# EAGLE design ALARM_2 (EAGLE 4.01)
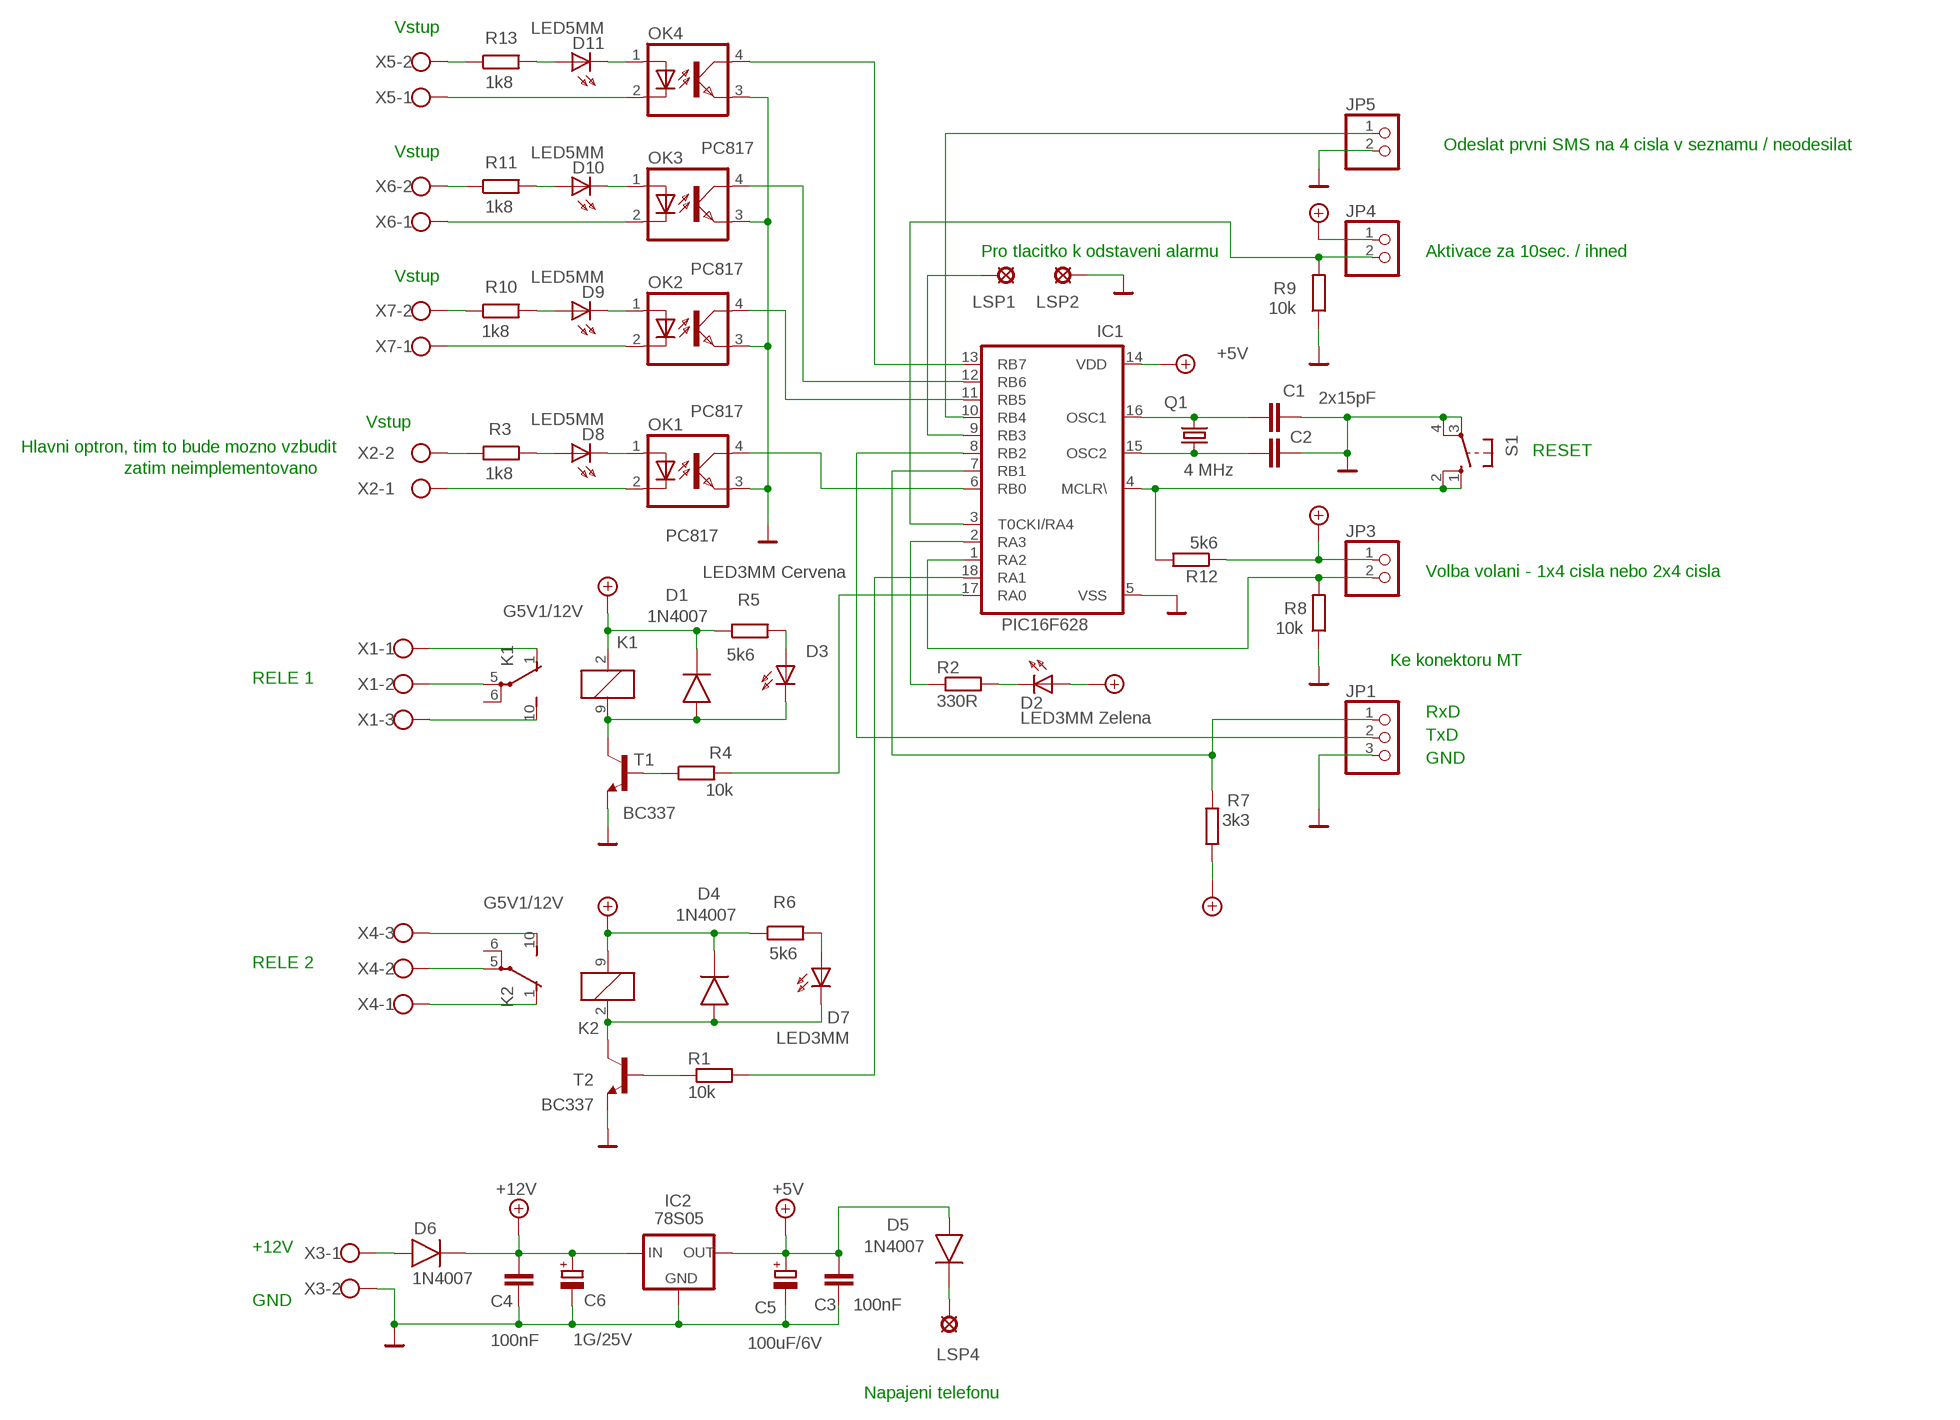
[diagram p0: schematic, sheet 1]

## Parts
C1  2x15pF  C-EU025-025X050  [C025-025X050]
C2  C-EU025-025X050  [C025-025X050]
C3  100nF  C-EU025-025X050  [C025-025X050]
C4  100nF  C-EU025-025X050  [C025-025X050]
C5  100uF/6V  CPOL-EUE2.5-7  [E2,5-7]
C6  1G/25V  CPOL-EUE5-13  [E5-13]
D1  1N4007  [DO41]
D2  LED3MM Zelena  LED3MM  [LED3MM]
D3  LED3MM Cervena  LED3MM  [LED3MM]
D4  1N4007  [DO41]
D5  1N4007  [DO41]
D6  1N4007  [DO41]
D7  LED3MM  [LED3MM]
D8  LED5MM  [LED5MM]
D9  LED5MM  [LED5MM]
D10  LED5MM  [LED5MM]
D11  LED5MM  [LED5MM]
IC1  PIC16F628  PIC16F84AP  [DIL18]
IC2  78S05  78XXS  [78XXS]
JP1  PINHD-1X3  [1X03]
JP3  PINHD-1X2  [1X02]
JP4  PINHD-1X2  [1X02]
JP5  PINHD-1X2  [1X02]
K1  G5V1/12V  G5V1  [G5V1]
K2  G5V1/12V  G5V1  [G5V1]
LSP1  LSP10  [LSP10]
LSP2  LSP10  [LSP10]
LSP4  LSP10  [LSP10]
OK1  PC817  [DIL04]
OK2  PC817  [DIL04]
OK3  PC817  [DIL04]
OK4  PC817  [DIL04]
Q1  4 MHz  HC49U-V  [HC49U-V]
R1  10k  R-EU_0207/10  [0207/10]
R2  330R  R-EU_0207/10  [0207/10]
R3  1k8  R-EU_0207/10  [0207/10]
R4  10k  R-EU_0207/10  [0207/10]
R5  5k6  R-EU_0207/10  [0207/10]
R6  5k6  R-EU_0207/10  [0207/10]
R7  3k3  R-EU_0207/10  [0207/10]
R8  10k  R-EU_0207/10  [0207/10]
R9  10k  R-EU_0207/10  [0207/10]
R10  1k8  R-EU_0207/10  [0207/10]
R11  1k8  R-EU_0207/10  [0207/10]
R12  5k6  R-EU_0207/10  [0207/10]
R13  1k8  R-EU_0207/10  [0207/10]
S1  10-XX  [B3F-10XX]
T1  BC337  [TO92]
T2  BC337  [TO92]
X1  AK500/3  [AK500/3]
X2  AK500/2  [AK500/2]
X3  AK500/2  [AK500/2]
X4  AK500/3  [AK500/3]
X5  AK500/2  [AK500/2]
X6  AK500/2  [AK500/2]
X7  AK500/2  [AK500/2]

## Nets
0V: C1.1 C2.1 C3.1 C4.1 C5.- C6.- IC1.5(VSS) IC2.GND JP1.3 JP5.2 LSP2.MP OK1.3(EMIT) OK2.3(EMIT) OK3.3(EMIT) OK4.3(EMIT) R8.1 R9.1 S1.3(P) S1.4(P1) T1.1(E) T2.1(E) X3.2
+5V: C3.2 C5.+ D2.A D5.A IC1.14(VDD) IC2.OUT JP3.1 JP4.1 R7.1 R12.1
+12V: C4.2 C6.+ D1.K D4.K D6.K IC2.IN K1.2 K2.9 R5.1 R6.1
N$1: C1.2 IC1.16(OSC1) Q1.2
N$2: C2.2 IC1.15(OSC2) Q1.1
N$3: R3.2 X2.2
N$4: OK1.2(C) X2.1
N$5: IC1.9(RB3) LSP1.MP
N$6: K1.5(2:P) X1.2
N$7: K1.1(2:O) X1.1
N$8: IC1.17(RA0) R4.2
N$9: IC1.6(RB0) OK1.4(COL)
N$10: D4.A D7.K(C) K2.2 T2.3(C)
N$11: K2.10(2:S) X4.3
N$12: R1.1 T2.2(B)
N$13: IC1.1(RA2) JP3.2 R8.2
N$14: OK2.2(C) X7.1
N$15: IC1.3(T0CKI/RA4) JP4.2 R9.2
N$16: K1.10(2:S) X1.3
N$17: IC1.2(RA3) R2.1
N$18: D2.K(C) R2.2
N$19: D1.A D3.K(C) K1.9 T1.3(C)
N$20: K2.5(2:P) X4.2
N$21: D6.A X3.1
N$22: D7.A R6.2
N$23: D3.A R5.2
N$24: R10.1 X7.2
N$25: R4.1 T1.2(B)
N$26: IC1.7(RB1) JP1.1 R7.2
N$27: IC1.8(RB2) JP1.2
N$28: R11.1 X6.2
N$29: IC1.18(RA1) R1.2
N$30: K2.1(2:O) X4.1
N$31: IC1.10(RB4) JP5.1
N$33: OK3.2(C) X6.1
N$34: D11.A R13.2
N$35: D11.K(C) OK4.1(A)
N$36: D10.A R11.2
N$37: D10.K(C) OK3.1(A)
N$38: IC1.11(RB5) OK2.4(COL)
N$39: IC1.12(RB6) OK3.4(COL)
N$40: D9.A R10.2
N$41: D9.K(C) OK2.1(A)
N$42: D8.A R3.1
N$43: OK4.2(C) X5.1
N$44: R13.1 X5.2
N$46: D8.K(C) OK1.1(A)
N$47: D5.K LSP4.MP
N$48: IC1.4(MCLR\) R12.2 S1.1(S) S1.2(S1)
N$49: IC1.13(RB7) OK4.4(COL)
Unconnected: K1.6(2:P) K2.6(2:P)

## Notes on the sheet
- Vstup
- Odeslat prvni SMS na 4 cisla v seznamu / neodesilat
- Vstup
- Pro tlacitko k odstaveni alarmu | Aktivace za 10sec. / ihned
- Vstup
- Vstup
- Hlavni optron, tim to bude mozno vzbudit | RESET
- zatim neimplementovano
- Volba volani - 1x4 cisla nebo 2x4 cisla
- Ke konektoru MT
- RELE 1
- RxD
- TxD
- GND
- RELE 2
- +12V
- GND
- Napajeni telefonu

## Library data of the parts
C1-C4 = rcl:C-EU: CAPACITOR, European symbol
C5 C6 = rcl:CPOL-EU: POLARIZED CAPACITOR, European symbol
D1 D4-D6 = GM99:1N4007
D2 D3 D7 = led:LED3MM: LED
D8-D11 = led:LED5MM: LED
IC1 = microchip:PIC16F8*: MICROCONTROLLER 8-Bit PIC16F8X Family - CMOS Flash/EEPROM Pin Compatible : PIC16F83, PIC16CR83, PIC16F84A, PIC16CR84 see also PIC16C*
IC2 = v-reg:78XXS: VOLTAGE REGULATOR
JP1 = pinhead:PINHD-1X3: PIN HEADER
JP3-JP5 = pinhead:PINHD-1X2: PIN HEADER
K1 K2 = relay:G5V1: RELAY 1 x switch, 0.5 A/125 V AC, 1 A/24 V DC , Omron
LSP1 LSP2 LSP4 = solpad:LSP10: SOLDER PAD
OK1-OK4 = optocoupler:PC817: SHARP OPTO COUPLER
Q1 = crystal:HC49U-V: CRYSTAL
R1-R13 = rcl:R-EU_: RESISTOR, European symbol
S1 = switch-omron:10-XX: OMRON SWITCH
T1 T2 = transistor-npn:BC337: NPN TRANSISTOR
X1 X4 = con-ptr500:AK500/3: CONNECTOR
X2 X3 X5-X7 = con-ptr500:AK500/2: CONNECTOR

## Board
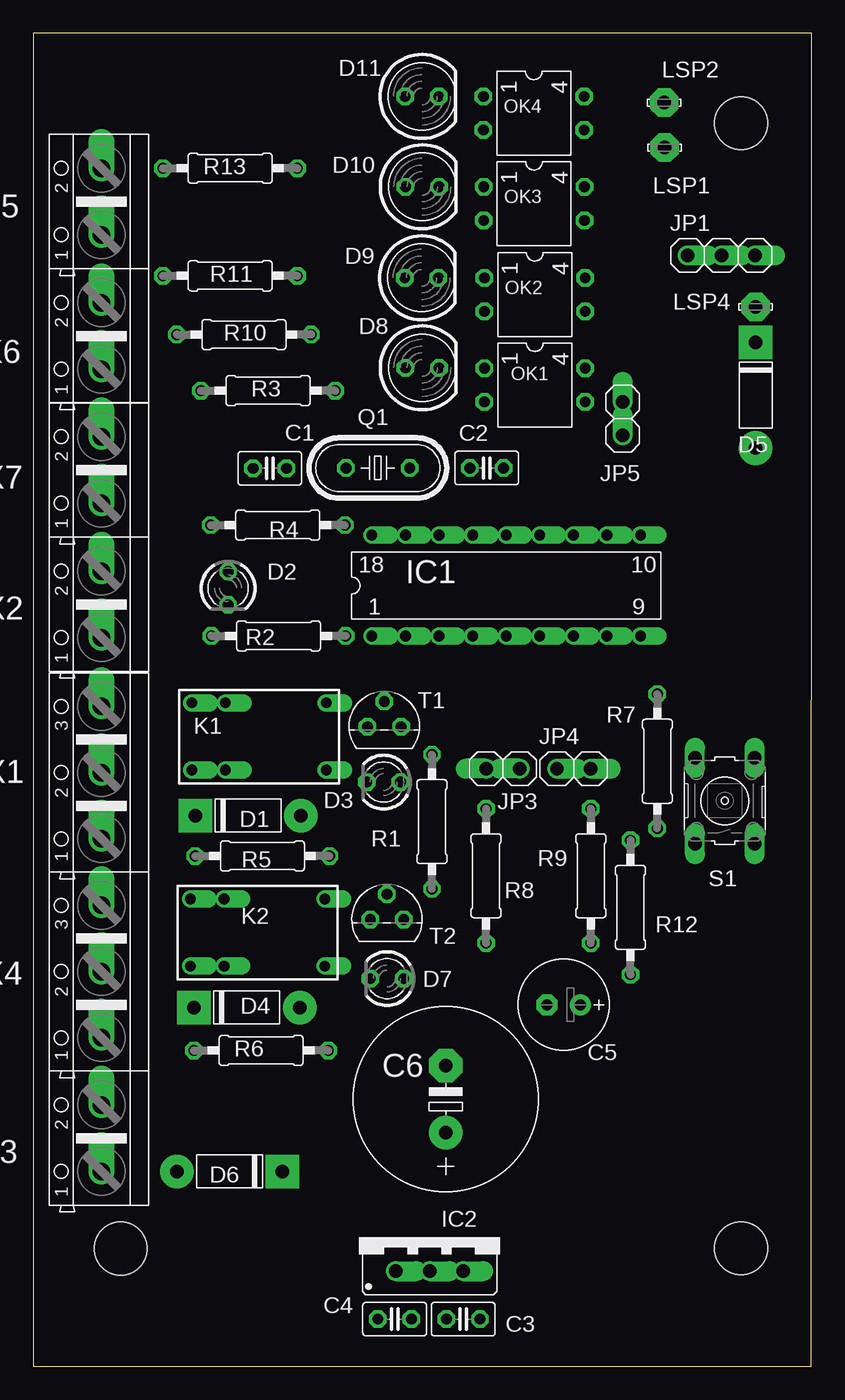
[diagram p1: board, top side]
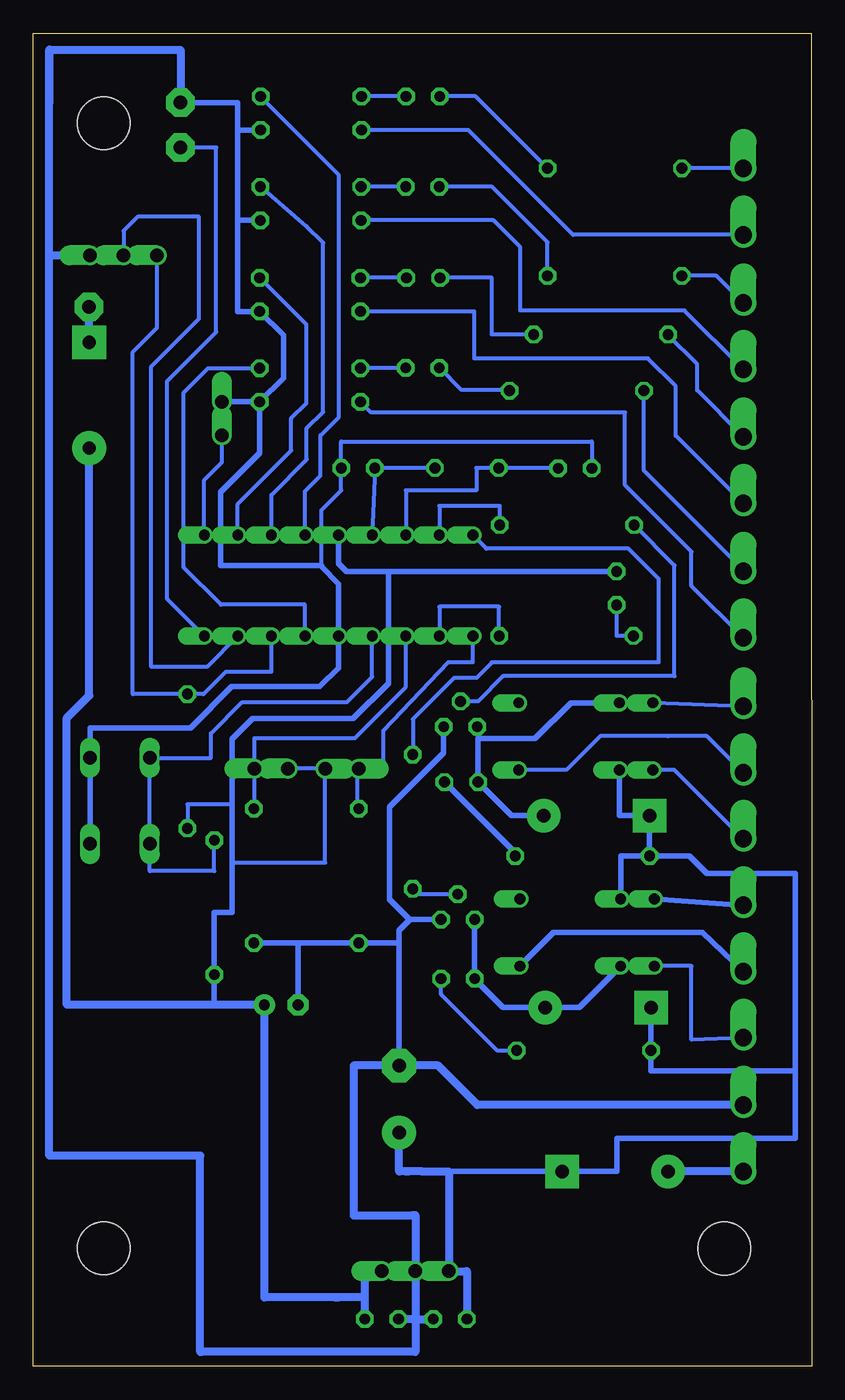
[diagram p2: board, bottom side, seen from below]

Size 58.89 x 100.82 mm. Coordinates in mm from the lower left corner, seen from the top.
Outline: 0,0 58.87,0.02 58.89,100.82 0.03,100.82 0,0
Copper layers used: Bottom
Holes 4 mm at 53.55,94.01 6.62,8.9 53.55,8.93

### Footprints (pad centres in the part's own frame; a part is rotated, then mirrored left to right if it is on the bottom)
C025-025X050 = drill 0.813 octagon: 1 -1.27,0; 2 1.27,0
E2,5-7 = drill 0.813 pad 1.6 round: + -1.27,0 | drill 0.813 pad 1.6 octagon: - 1.27,0
E5-13 = drill 1.016 pad 2.54 round: + -2.54,0 | drill 1.016 pad 2.54 octagon: - 2.54,0
DO41 = drill 1.016 pad 2.54 round: A 8,0 | drill 1.016 pad 2.54 square: K 0,0
LED3MM = drill 0.813 octagon: A -1.27,0; K 1.27,0
LED5MM = drill 0.813 octagon: A -1.27,0; K 1.27,0
DIL18 = drill 0.813 offset: 1 -10.16,-3.81; 2 -7.62,-3.81; 3 -5.08,-3.81; 4 -2.54,-3.81; 5 0,-3.81; 6 2.54,-3.81; 7 5.08,-3.81; 8 7.62,-3.81; 9 10.16,-3.81; 10 10.16,3.81; 11 7.62,3.81; 12 5.08,3.81; 13 2.54,3.81; 14 0,3.81; 15 -2.54,3.81; 16 -5.08,3.81; 17 -7.62,3.81; 18 -10.16,3.81
78XXS = drill 1.016 offset: GND 0,-2.54; IN -2.54,-2.54; OUT 2.54,-2.54
1X03 = drill 1.016 offset: 1 -2.54,0; 2 0,0; 3 2.54,0
1X02 = drill 1.016 offset: 1 -1.27,0; 2 1.27,0
G5V1 = drill 0.813 offset: 1 -5.08,-2.54; 2 -2.54,-2.54; 5 5.08,-2.54; 6 5.08,2.54; 9 -2.54,2.54; 10 -5.08,2.54
LSP10 = drill 1.016 pad 2.159 octagon: MP 0,0
DIL04 = drill 0.813 octagon: 1 -1.27,-3.81; 2 1.27,-3.81; 3 1.27,3.81; 4 -1.27,3.81
HC49U-V = drill 0.813 octagon: 1 -2.413,0; 2 2.413,0
0207/10 = drill 0.813 octagon: 1 -5.08,0; 2 5.08,0
B3F-10XX = drill 1.016 long: 1 -3.251,2.261; 2 3.251,2.261; 3 -3.251,-2.261; 4 3.251,-2.261
TO92 = drill 0.813 octagon: 1 1.27,0; 2 0,1.905; 3 -1.27,0
AK500/3 = drill 1.321 offset: 1 -5.004,0; 2 0,0; 3 5.004,0
AK500/2 = drill 1.321 offset: 1 -2.515,0; 2 2.515,0

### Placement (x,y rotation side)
C1  17.9,67.91 0 top
C2  34.31,67.93 180 top
C3  32.53,3.58 0 top
C4  27.35,3.58 180 top
C5  40.13,27.34 180 top
C6  31.21,20.21 90 top
D1  12.26,41.65 0 top
D2  14.75,58.84 270 top
D3  26.51,44.19 180 top
D4  12.16,27.14 0 top
D5  54.65,77.44 270 top
D6  18.87,14.75 180 top
D7  26.77,29.33 180 top
D8  29.43,75.5 0 top
D9  29.38,82.31 0 top
D10  29.43,89.19 0 top
D11  29.41,96.02 0 top
IC1  35.78,59.04 0 top
IC2  29.99,9.75 0 top
JP1  52.06,84.01 0 top
JP3  35.53,45.2 180 top
JP4  40.89,45.2 0 top
JP5  44.6,71.67 90 top
K1  17.09,47.64 0 top
K2  16.99,32.81 0 top
LSP1  47.76,92.16 0 top
LSP2  47.74,95.56 0 top
LSP4  54.65,80.12 0 top
OK1  37.94,74.21 270 top
OK2  37.94,81.04 270 top
OK3  37.89,87.92 270 top
OK4  37.87,94.76 270 top
Q1  26.08,67.93 180 top
R1  30.17,41.19 90 top
R2  18.56,55.23 180 top
R3  17.77,73.78 180 top
R4  18.51,63.62 0 top
R5  17.34,38.6 0 top
R6  17.24,23.89 0 top
R7  47.21,45.76 90 top
R8  34.26,37.1 90 top
R9  42.18,37.1 90 top
R10  15.95,78.02 0 top
R11  14.9,82.46 0 top
R12  45.18,34.71 90 top
R13  14.9,90.59 0 top
S1  52.32,42.76 90 top
T1  26.56,48.38 0 top
T2  26.77,33.8 0 top
X1  5.18,44.9 90 top
X2  5.18,57.62 90 top
X3  5.18,17.26 90 top
X4  5.18,29.86 90 top
X5  5.18,88.08 90 top
X6  5.18,77.92 90 top
X7  5.18,67.78 90 top

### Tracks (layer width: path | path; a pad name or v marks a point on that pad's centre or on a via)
0V
  Bottom 0.305: C1.1 16.63,69.94 35.58,69.94 C2.1 35.58,66.23 37.08,64.73 37.08,60.57 37.08,60.47 | 30.4,33.8 30.42,33.8 | 31.21,31.92 31.21,32.02 | R9.1 40.53,32.02 | 43.4,93.46 43.4,93.49 | 43.4,83.4 43.4,83.42 | 43.4,88.97 43.4,88.5 | JP5.2 44.62,72.94 | 54.58,45.96 S1.4 | 54.55,48.27 54.58,48.25 | 39.57,32.02 38.86,32.02
  Bottom 0.406: 37.08,60.47 35.78,59.17 IC1.5 35.78,52.82 37.21,51.4 43.86,51.4 46.99,48.27 54.55,48.27 | 43.4,93.49 OK4.3 | 43.4,86.65 43.4,88.97 43.4,93.46 43.4,95.56 LSP2.MP | 43.4,86.65 OK3.3 | T1.1 27.83,46.39 31.92,42.31 31.92,35.3 30.42,33.8 | T2.1 30.4,33.8 31.21,32.98 31.21,31.92 C6.- | 31.21,32.02 R8.1 39.57,32.02 | 43.4,86.65 43.4,83.4 43.4,79.77 OK2.3 39.95,77.97 39.95,74.74 OK1.3 | S1.3 54.58,45.96 54.58,48.25 | 39.57,32.02 R9.1 | 39.57,32.02 36.95,32.02 | 37.08,60.57 44.72,60.57 44.72,66.11 41.75,69.08 OK1.3 | OK1.3 JP5.2 | 38.86,32.02 C5.-
  Bottom 0.61: X3.2 25.29,19.78 28.27,22.75 C6.- 34.64,22.75 34.64,11.42 29.99,11.44 | IC2.GND 29.99,3.59 29.95,3.59 29.95,3.57 | C4.1 29.95,3.57 | C3.1 29.95,3.57 | 57.65,84.01 JP1.3 | IC2.GND 29.99,1.1 46.17,1.1 46.25,1.1 46.25,15.93 57.65,15.93 57.65,84.01 | 57.65,99.56 57.65,95.57 | 57.65,84.01 57.65,99.56 | 29.99,11.44 30.17,11.44 | IC2.GND 29.99,11.44 | 57.65,99.56 | LSP2.MP 47.74,99.56 57.65,99.56
+5V
  Bottom 0.305: 36.8,45 JP3.1 36.8,45.23 | 39.62,45.23 39.7,45.23 | 39.62,45.23 JP4.1 | 36.8,45.23 39.62,45.23 | 36.8,45.23 36.8,38.09 43.84,38.09 | 32.02,60.09 32,60.09 31.97,60.11 | R7.1 47.21,42.51 43.84,42.51 | C5.+ 45.18,27.34
  Bottom 0.406: D2.A 31.97,60.11 35.2,60.11 35.78,60.7 IC1.14 | 32.02,60.09 32.02,51.65 34.69,48.99 42.29,48.99 43.84,47.44 43.84,42.51 43.84,38.09 43.84,34.33 45.18,34.33 R12.1 45.18,27.34
  Bottom 0.61: D5.A 54.65,50.72 56.33,49.04 56.33,27.34 C5.+ 41.4,5.21 35.81,5.21 35.81,5.22 | 35.81,5.22 36.04,5.22 | C3.2 33.8,5.22 | 33.8,5.22 35.81,5.22 | 33.8,7.21 IC2.OUT | 33.8,7.21 33.8,7.23 | 33.8,5.22 33.8,7.21
+12V
  Bottom 0.305: D1.K 12.26,41.67 | 12.59,38.6 R5.1 | D4.K R6.1 | 1.27,22.39 1.27,22.34
  Bottom 0.406: K1.2 14.55,41.67 12.26,41.67 | R5.1 D1.K | K2.9 14.45,38.6 12.59,38.6 9.24,38.6 7.92,37.28 1.27,37.28 1.27,22.39 1.27,17.26 14.73,17.26 14.73,14.75 D6.K 29.45,14.75 | D4.K 12.16,22.34 1.27,22.34
  Bottom 0.61: 30.53,14.75 30.7,14.75 | C6.+ 31.21,14.75 30.53,14.75 | 30.53,14.75 29.45,14.75 27.45,14.75 IC2.IN 26.08,7.21 C4.2 | C4.2 | C4.2
N$1
  Bottom 0.305: C1.2 19.17,67.93 Q1.2 25.37,67.93 25.37,66.23 30.7,66.23 IC1.16
N$2
  Bottom 0.305: Q1.1 C2.2 IC1.15
N$3
  Bottom 0.305: 5.15,60.19 5.1,60.14 | X2.2 5.15,60.19 | R3.2 12.7,67.73 5.15,60.19
N$4
  Bottom 0.305: X2.1 9.09,59.02 9.09,61.61 14.12,66.64 14.12,72.13 33.32,72.13 OK1.2
N$5
  Bottom 0.305: LSP1.MP 45.03,92.16 45.03,78.22 48.74,74.51 48.74,58.03 IC1.9
N$6
  Bottom 0.305: K1.5 18.56,45.1 16,47.66 10.89,47.66 | 10.89,47.66 10.87,47.66 | X1.2 7.95,47.66 10.89,47.66
N$7
  Bottom 0.305: 5.18,39.87 5.15,39.84 | X1.1 5.18,39.87 | K1.1 10.41,45.1 5.18,39.87
N$8
  Bottom 0.305: IC1.17 28.16,65.06 23.59,65.06 R4.2
N$9
  Bottom 0.305: IC1.6 38.32,57.6 44.67,57.6 47.49,60.42 47.49,73.65 45.66,75.48 OK1.4
N$10
  Bottom 0.305: 25.5,29.3 D7.K | D4.A
  Bottom 0.406: D7.K T2.3 | 25.5,29.3 23.34,27.14 D4.A 17.57,27.14 K2.2
N$11
  Bottom 0.406: K2.10 11.93,35.35 X4.3
N$12
  Bottom 0.305: R1.1 30.17,35.7 T2.2
N$13
  Bottom 0.305: 34.34,45.18 34.29,45.18 JP3.2 | R8.2 34.29,42.15 34.34,42.15 34.34,45.12 JP3.2 | IC1.1 25.62,53.25 27.48,53.25 32.41,48.07 32.41,45.2 34.31,45.2 | 34.31,45.2 34.34,45.2 | JP3.2 34.31,45.2
N$14
  Bottom 0.305: OK2.2 25.52,79.77 25.52,76.21 12.39,76.21 10.28,74.11 10.28,70.37 X7.1
N$15
  Bottom 0.305: JP4.2 42.16,45.12 | R9.2 42.16,42.15 JP4.2 | IC1.3 30.7,51.37 34.59,47.49 42.16,47.49 JP4.2
N$16
  Bottom 0.305: K1.10 12.01,50.15 X1.3
N$17
  Bottom 0.305: IC1.2 28.16,57.44 23.64,57.44 R2.1 23.64,55.21
N$18
  Bottom 0.305: D2.K 14.75,55.23 R2.2
N$19
  Bottom 0.305: T1.3 25.24,48.38 25.24,47.46
  Bottom 0.406: D1.A 22.7,41.65 D3.K 25.24,47.46 20.92,47.46 18.21,50.18 K1.9
N$20
  Bottom 0.406: X4.2 8.28,32.81 19.53,32.81 K2.5
N$21
  Bottom 0.61: D6.A X3.1
N$22
  Bottom 0.305: D7.A 28.04,28.13 23.77,23.87 22.32,23.87 R6.2
N$23
  Bottom 0.406: D3.A 22.42,38.83 R5.2
N$24
  Bottom 0.305: R10.1 10.87,77.99 8.66,75.78 8.66,73.8 5.18,70.32 X7.2
N$25
  Bottom 0.305: 13.48,63.67 R4.1 10.38,60.57 10.38,52.19 23.34,52.19 25.24,50.28 T1.2
N$26
  Bottom 0.305: IC1.7 40.86,52.52 44.32,52.52 45.99,50.84 R7.2 51.35,50.84 51.35,76.7 | 51.35,76.7 | JP1.1 49.52,78.53 51.35,76.7
N$27
  Bottom 0.305: IC1.8 45.74,52.9 48.92,52.9 | 48.92,52.9 48.97,52.9 | 48.92,52.9 49.96,52.9 49.96,75.6 46.35,79.21 46.35,86.93 51,86.93 52.06,85.87 JP1.2
N$28
  Bottom 0.305: 9.82,82.49 R11.1 7.21,82.46 X6.2
N$29
  Bottom 0.305: IC1.18 24.61,61.84 13.86,61.84 11.58,59.55 11.58,53.23 24.18,53.23 | R1.2 30.17,48.93 27.05,52.06 25.34,52.06 24.18,53.23 | 24.18,53.23 24.2,53.23
N$30
  Bottom 0.305: K2.1 9.09,30.27 9.09,24.7 X4.1
N$31
  Bottom 0.305: IC1.10 45.94,67.02 44.6,68.37 JP5.1
N$33
  Bottom 0.305: OK3.2 24.07,86.65 22.04,84.62 22.04,79.85 9.62,79.85 X6.1
N$34
  Bottom 0.305: D11.A 25.42,96.02 R13.2
N$35
  Bottom 0.305: OK4.1 34.03,96.03 34.03,96.02 D11.K
N$36
  Bottom 0.305: D10.A 24.18,89.19 19.98,85 R11.2
N$37
  Bottom 0.305: D10.K OK3.1
N$38
  Bottom 0.305: IC1.11 43.4,65.22 39.37,69.25 39.37,71.69 38.22,72.84 38.22,78.78 39.39,79.95 | 39.39,79.95 OK2.4 | 39.39,79.95 39.37,79.92
N$39
  Bottom 0.305: OK3.4 38.2,86.2 36.95,84.95 36.95,72.18 38.2,70.93 38.2,68.57 40.86,65.9 IC1.12
N$40
  Bottom 0.305: 24.2,79.69 24.2,82.31 D9.A | 24.2,79.69 24.2,79.67 | R10.2 24.2,78.02 24.2,79.69
N$41
  Bottom 0.305: D9.K OK2.1
N$42
  Bottom 0.305: R3.1 22.83,73.8 22.83,73.83 26.49,73.83 D8.A
N$43
  Bottom 0.305: X5.1 18.05,85.56 25.98,93.49 OK4.2
N$44
  Bottom 0.305: X5.2 R13.1
N$46
  Bottom 0.305: D8.K 30.73,75.48 OK1.1
N$47
  Bottom 0.61: D5.K | D5.K LSP4.MP | D5.K 54.66,77.43
N$48
  Bottom 0.305: IC1.4 33.24,52.14 35.15,50.23 43.07,50.23 45.44,47.87 45.44,46.01 S1.2 50.06,39.54 | R12.2 45.18,37.45 50.06,37.45 50.06,39.54 | 50.06,39.54 S1.1
N$49
  Bottom 0.305: IC1.13 38.32,66.18 37.16,67.35 37.16,70.4 35.76,71.79 35.76,90.06 41.7,96 OK4.4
